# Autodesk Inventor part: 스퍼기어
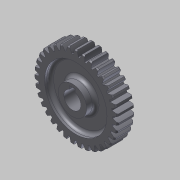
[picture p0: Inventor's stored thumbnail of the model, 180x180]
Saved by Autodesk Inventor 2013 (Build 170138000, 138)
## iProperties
Created: 2013-08
Part Number: 스퍼기어
Material: 강
Document SubType Name: Modeling
Designer: 한국산업디자인학원
Categories: <?xml version="1.0" encoding="UTF-16"?> <MemberInstance><Categories><FamilyTemplate><FamilyTemplateParameter ValueType="xs:double" Id="1" ObjectReferenceKey="da
Density: 1 g/cm^3
CustomPartVersion: 1
Author: 한국산업디자인학원
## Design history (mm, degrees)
sketch "Sketch1"
  geometry: C1 r 37 at (0, 0)
  constraints: 1 centre point
  dimensions: "d0" = 74 diameter of C1 (= da_da)
extrude "Extrusion1" new body sketch "Sketch1" distance "d1" = 15 (= da_b); taper "d2" = 0 deg
chamfer "모따기1" distance "d49" = 1; stored, may be unused: second distance "d50" = 2, angle "d51" = 45 deg
workplane "Work Plane2"
feature "피치 지름" dims "d4" = 10, "d5" = 0
workplane "Work Plane8"
workplane "Work Plane9"
feature "스퍼 기어" dims "da_b" = 15, "da_d" = 70, "da_aw" = 70, "da_da" = 74, "da_df" = 65, "da_dw" = 70, angle "da_beta" = 0 deg, "da_lefttooth" = 0, "da_righttooth" = 0
sketch "스케치3"
  geometry: C1 r 12.5 at (0, 0); C2 r 7.5 at (0, 0); C3 r 27.5 at (0, 0); A1 r 36 centre (0, 0) between (-5.215, 35.62) and (-7.633, 35.181) reference
  constraints: 3 centre point, 3 coincident
  dimensions: "d52" = 25 diameter of C1; "d53" = 15 diameter of C2; "d54" = 55 diameter of C3
extrude "돌출2" cut sketch "스케치3" distance "d55" = 5; taper "d56" = 0 deg
sketch "스케치4"
  geometry: C1 r 27.5 at (0, 0); C2 r 12.5 at (0, 0); A1 r 32.5 centre (0, 0) between (9.347, 31.127) and (7.941, 31.515) reference
  constraints: 2 centre point, 2 coincident
  dimensions: "d57" = 55 diameter of C1; "d58" = 25 diameter of C2
extrude "돌출3" cut sketch "스케치4" distance "d59" = 5; taper "d60" = 0 deg
extrude "돌출4" join sketch "스케치3" distance "d61" = 3; taper "d63" = 0 deg; dims "d62" = 28, "d64" = 0
extrude "돌출5" cut sketch "스케치3" stored distance "d65" = 3; taper "d66" = 0 deg
sketch "스케치5"
  geometry: L1 (-2.5, 9.8)-(2.5, 9.8); L2 (2.5, 9.8)-(2.5, 4.8); L3 (2.5, 4.8)-(-2.5, 4.8); L4 (-2.5, 4.8)-(-2.5, 9.8); C1 r 7.5 at (0, 0) reference; 1 further point
  constraints: 8 end point, 2 parallel, 1 horizontal, 1 midpoint, 1 perpendicular, 1 vertical alignment
  dimensions: "d67" = 5 distance of L1.start L1.end; "d69" = 17.3 dimension on C1 L1; "d70" = 5 distance of L1.end L2.end
extrude "돌출6" cut sketch "스케치5" stored distance "d71" = 3; taper "d72" = 0 deg
fillet "모깎기1" dims "d73" = 3
body "Solid1"
sketch "Sketch2"
  geometry: C1 r 37 at (0, 0) reference; C2 r 35 at (0, 0)
  constraints: 1 centre point, 1 coincident
  dimensions: "d3" = 70 diameter of C2 (= da_dw)
body "Srf1"
other parameters: "d17" = 0, "d34" = 0.8976 (computed from da_z), "d39" = 0, "d41" = 0, "d47" = 0, "d48" = 0
